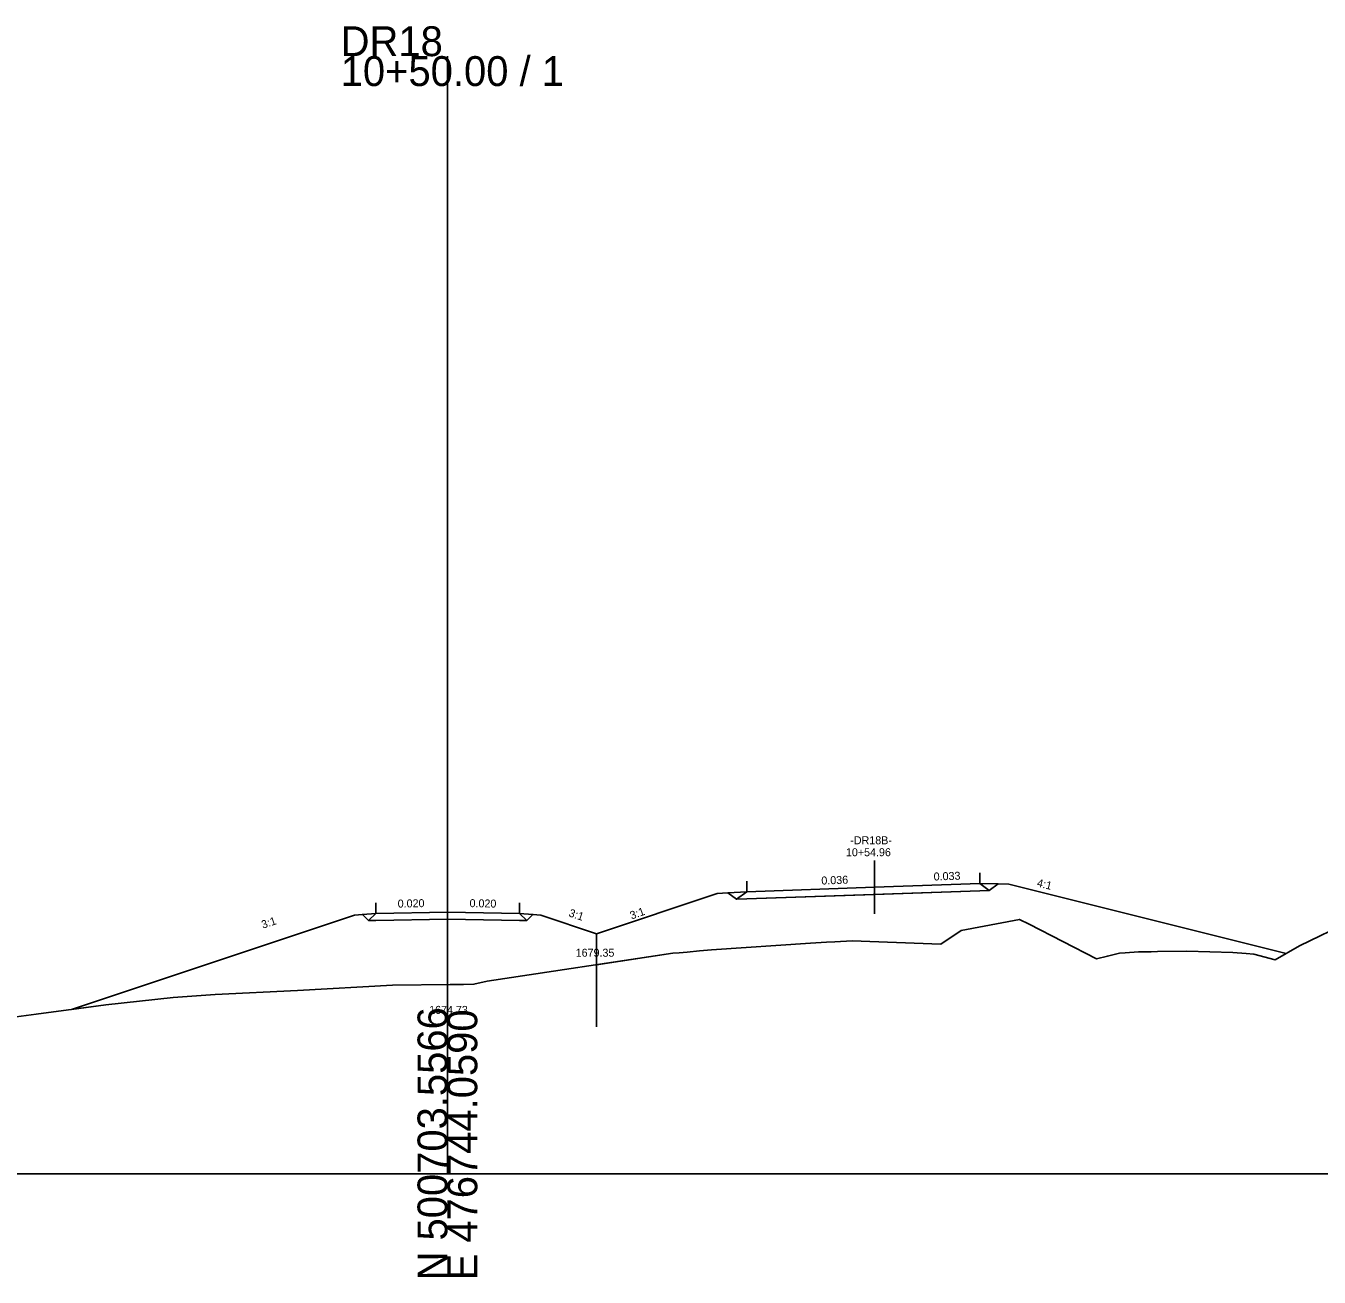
# Model space of a CAD drawing. Extents: x -26 to 403, y -10 to 2113.
# Drawn here: x 160.5 to 281.7, y 990.3 to 1107.6 of the extents above; entities that cross this region are included whole.
import ezdxf

# ---------------------------------------------------------------- set-up
doc = ezdxf.new("R2010")
doc.units = 0
for name, color, linetype in [('Exist Cross Section Cell', 7, 'Continuous'), ('Exist XS Center Line Elevation Label', 7, 'Continuous'), ('Exist XS Ground Line', 7, 'Continuous'), ('Prop XS Earthwork Shape', 7, 'Continuous'), ('Prop XS EOT Tick Mark', 7, 'Continuous'), ('Prop XS Finish Grade', 7, 'Continuous'), ('Prop XS Finish Grade Earthwork', 7, 'Continuous'), ('Prop XS Finish Grade Pavement', 7, 'Continuous'), ('Prop XS Pvmt Edge Slope', 7, 'Continuous'), ('Prop XS SE Text', 7, 'Continuous'), ('Prop XS Shoulder Borrow Shape', 7, 'Continuous'), ('Prop XS Side Slope Text', 7, 'Continuous'), ('Prop XS Station Labels', 7, 'Continuous'), ('Prop XS Subgrade Earthwork', 7, 'Continuous'), ('Scratch_Level_9', 7, 'Continuous')]:
    doc.layers.add(name, color=color, linetype=linetype)

msp = doc.modelspace()

# ---------------------------------------------------------------- linework, layer by layer
at = {"layer": 'Exist Cross Section Cell'}
for p, q in [((200, 1000), (200, 1104.75)), ((0, 1000), (200, 1000)), ((200, 1000), (400, 1000))]:
    msp.add_line(p, q, dxfattribs=at)
at = {"layer": 'Exist XS Ground Line'}
msp.add_lwpolyline([(158.65, 1014.58), (161.47, 1014.95), (167.99, 1015.84), (174.3, 1016.53), (178.24, 1016.81), (185.95, 1017.16), (194.86, 1017.67), (200.27, 1017.73), (201.5, 1017.75), (202.49, 1017.76), (203.74, 1018.04), (221.13, 1020.66), (221.73, 1020.72), (222.46, 1020.78), (223.61, 1020.9), (224.73, 1020.99), (234.02, 1021.62), (235.51, 1021.71), (236.29, 1021.74), (237.92, 1021.84), (246.23, 1021.53), (248.15, 1022.81), (253.59, 1023.83), (254.51, 1023.4), (260.81, 1020.15), (261.83, 1020.4), (262.96, 1020.66), (263.51, 1020.7), (264.75, 1020.8), (265.43, 1020.8), (265.95, 1020.81), (266.53, 1020.82), (269.29, 1020.86), (273.6, 1020.75), (274.84, 1020.64), (275.57, 1020.57), (277.54, 1020.06), (279.82, 1021.36), (284.62, 1023.66)], dxfattribs=at)
at = {"layer": 'Prop XS Earthwork Shape'}
msp.add_lwpolyline([(249.89, 1026.52), (250.77, 1026.54), (251.59, 1027.16), (252.6, 1027.14), (278.57, 1020.64), (277.54, 1020.06), (275.57, 1020.57), (274.84, 1020.64), (273.6, 1020.75), (269.29, 1020.86), (266.53, 1020.82), (265.95, 1020.81), (265.43, 1020.8), (264.75, 1020.8), (263.51, 1020.7), (262.96, 1020.66), (261.83, 1020.4), (260.81, 1020.15), (254.51, 1023.4), (253.59, 1023.83), (248.15, 1022.81), (246.23, 1021.53), (237.92, 1021.84), (236.29, 1021.74), (235.51, 1021.71), (234.02, 1021.62), (224.73, 1020.99), (223.61, 1020.9), (222.46, 1020.78), (221.73, 1020.72), (221.13, 1020.66), (203.74, 1018.04), (202.49, 1017.76), (201.5, 1017.75), (200.27, 1017.73), (194.86, 1017.67), (185.95, 1017.16), (178.24, 1016.81), (174.3, 1016.53), (167.99, 1015.84), (164.79, 1015.4), (191.3, 1024.24), (192.04, 1024.3), (192.62, 1023.72), (193.3, 1023.73), (200, 1023.87), (206.75, 1023.73), (207.43, 1023.72), (208.01, 1024.3), (208.75, 1024.24), (213.97, 1022.5), (225.27, 1026.27), (226.27, 1026.32), (227.09, 1025.74), (228.05, 1025.76)], close=True, dxfattribs=at)
at = {"layer": 'Prop XS EOT Tick Mark'}
for p, q in [((249.89, 1027.19), (249.89, 1028.19)), ((228.05, 1026.43), (228.05, 1027.43)), ((193.3, 1024.4), (193.3, 1025.4)), ((206.75, 1024.4), (206.75, 1025.4))]:
    msp.add_line(p, q, dxfattribs=at)
at = {"layer": 'Prop XS Finish Grade'}
for p, q in [((228.05, 1026.43), (226.27, 1026.32)), ((249.89, 1027.19), (251.59, 1027.16)), ((193.3, 1024.4), (192.04, 1024.3)), ((206.75, 1024.4), (208.01, 1024.3))]:
    msp.add_line(p, q, dxfattribs=at)
at = {"layer": 'Prop XS Finish Grade Earthwork'}
for p, q in [((226.27, 1026.32), (225.27, 1026.27)), ((251.59, 1027.16), (252.6, 1027.14)), ((252.6, 1027.14), (278.57, 1020.64)), ((225.27, 1026.27), (213.97, 1022.5)), ((191.3, 1024.24), (164.79, 1015.4)), ((192.04, 1024.3), (191.3, 1024.24)), ((208.01, 1024.3), (208.75, 1024.24)), ((208.75, 1024.24), (213.97, 1022.5))]:
    msp.add_line(p, q, dxfattribs=at)
at = {"layer": 'Prop XS Finish Grade Pavement'}
for p, q in [((228.05, 1026.43), (240.02, 1026.86)), ((240.02, 1026.86), (249.89, 1027.19)), ((193.3, 1024.4), (200, 1024.53)), ((200, 1024.53), (206.75, 1024.4))]:
    msp.add_line(p, q, dxfattribs=at)
at = {"layer": 'Prop XS Pvmt Edge Slope'}
for p, q in [((228.05, 1026.43), (227.09, 1025.74)), ((249.89, 1027.19), (250.77, 1026.54)), ((193.3, 1024.4), (192.62, 1023.72)), ((206.75, 1024.4), (207.43, 1023.72))]:
    msp.add_line(p, q, dxfattribs=at)
at = {"layer": 'Prop XS Shoulder Borrow Shape'}
for points in [[(193.3, 1024.4), (192.62, 1023.72), (192.04, 1024.3)], [(207.43, 1023.72), (208.01, 1024.3), (206.75, 1024.4)]]:
    msp.add_lwpolyline(points, close=True, dxfattribs=at)
at = {"layer": 'Prop XS Station Labels'}
msp.add_line((240.02, 1029.36), (240.02, 1024.36), dxfattribs=at)
at = {"layer": 'Prop XS Subgrade Earthwork'}
for p, q in [((227.09, 1025.74), (226.27, 1026.32)), ((249.89, 1026.52), (228.05, 1025.76)), ((249.89, 1026.52), (250.77, 1026.54)), ((250.77, 1026.54), (251.59, 1027.16)), ((228.05, 1025.76), (227.09, 1025.74)), ((192.62, 1023.72), (192.04, 1024.3)), ((200, 1023.87), (193.3, 1023.73)), ((206.75, 1023.73), (200, 1023.87)), ((207.43, 1023.72), (208.01, 1024.3)), ((193.3, 1023.73), (192.62, 1023.72)), ((206.75, 1023.73), (207.43, 1023.72))]:
    msp.add_line(p, q, dxfattribs=at)
at = {"layer": 'Scratch_Level_9'}
for p, q in [((226.27, 1026.32), (225.27, 1026.27)), ((249.89, 1026.52), (240.02, 1026.18)), ((250.77, 1026.54), (249.89, 1026.52)), ((251.59, 1027.16), (250.77, 1026.54)), ((252.6, 1027.14), (251.59, 1027.16)), ((278.57, 1020.64), (252.6, 1027.14)), ((225.27, 1026.27), (213.97, 1022.5)), ((240.02, 1026.18), (228.05, 1025.76)), ((213.97, 1022.5), (213.97, 1013.76)), ((213.97, 1022.5), (213.97, 1019.58)), ((213.97, 1019.58), (221.13, 1020.66)), ((262.96, 1020.66), (263.51, 1020.7)), ((263.51, 1020.7), (264.75, 1020.8)), ((264.75, 1020.8), (265.43, 1020.8)), ((265.43, 1020.8), (265.95, 1020.81)), ((275.57, 1020.57), (277.54, 1020.06)), ((277.54, 1020.06), (278.57, 1020.64))]:
    msp.add_line(p, q, dxfattribs=at)
for points in [[(228.05, 1025.76), (227.09, 1025.74), (226.27, 1026.32)], [(237.92, 1021.84), (246.23, 1021.53), (248.15, 1022.81)], [(248.15, 1022.81), (253.59, 1023.83), (254.51, 1023.4), (260.81, 1020.15), (261.83, 1020.4), (262.96, 1020.66)], [(222.46, 1020.78), (223.61, 1020.9), (224.73, 1020.99), (234.02, 1021.62), (235.51, 1021.71)], [(235.51, 1021.71), (236.29, 1021.74), (237.92, 1021.84)], [(221.13, 1020.66), (221.73, 1020.72), (222.46, 1020.78)], [(265.95, 1020.81), (266.53, 1020.82), (269.29, 1020.86), (273.6, 1020.75), (274.84, 1020.64), (275.57, 1020.57)]]:
    msp.add_lwpolyline(points, dxfattribs=at)

# ---------------------------------------------------------------- texts
at = {"layer": 'Exist Cross Section Cell'}
for s, p in [('DR18', (190, 1104.75)), ('10+50.00 / 1', (190, 1101.95))]:
    msp.add_text(s, height=2.8, dxfattribs=at).set_placement(p)
for s, p in [('N 500703.5566', (200, 990)), ('E 476744.0590', (202.8, 990))]:
    msp.add_text(s, height=2.8, rotation=90, dxfattribs=at).set_placement(p)
at = {"layer": 'Exist XS Center Line Elevation Label'}
msp.add_text('1674.73', height=0.75, dxfattribs=at).set_placement((198.29, 1014.98))
at = {"layer": 'Prop XS SE Text'}
for s, rotation, p in [('0.036', 2.0856, (235.05, 1027.1)), ('0.033', 1.8966, (245.57, 1027.48)), ('0.020', 1.1458, (195.35, 1024.94)), ('0.020', 358.8542, (202.07, 1024.99))]:
    msp.add_text(s, height=0.75, rotation=rotation, dxfattribs=at).set_placement(p)
at = {"layer": 'Prop XS Side Slope Text'}
for s, rotation, p in [('4:1', 345.9638, (255.18, 1026.94)), ('3:1', 18.4349, (182.72, 1022.96)), ('3:1', 341.5651, (211.31, 1024.14)), ('3:1', 19.8172, (217.26, 1023.82)), ('1679.35', 360, (212.02, 1020.34))]:
    msp.add_text(s, height=0.75, rotation=rotation, dxfattribs=at).set_placement(p)
at = {"layer": 'Prop XS Station Labels'}
for s, p in [(' -DR18B-', (237.47, 1030.88)), (' 10+54.96', (237.06, 1029.76))]:
    msp.add_text(s, height=0.75, dxfattribs=at).set_placement(p)

doc.saveas('drawing.dxf')
